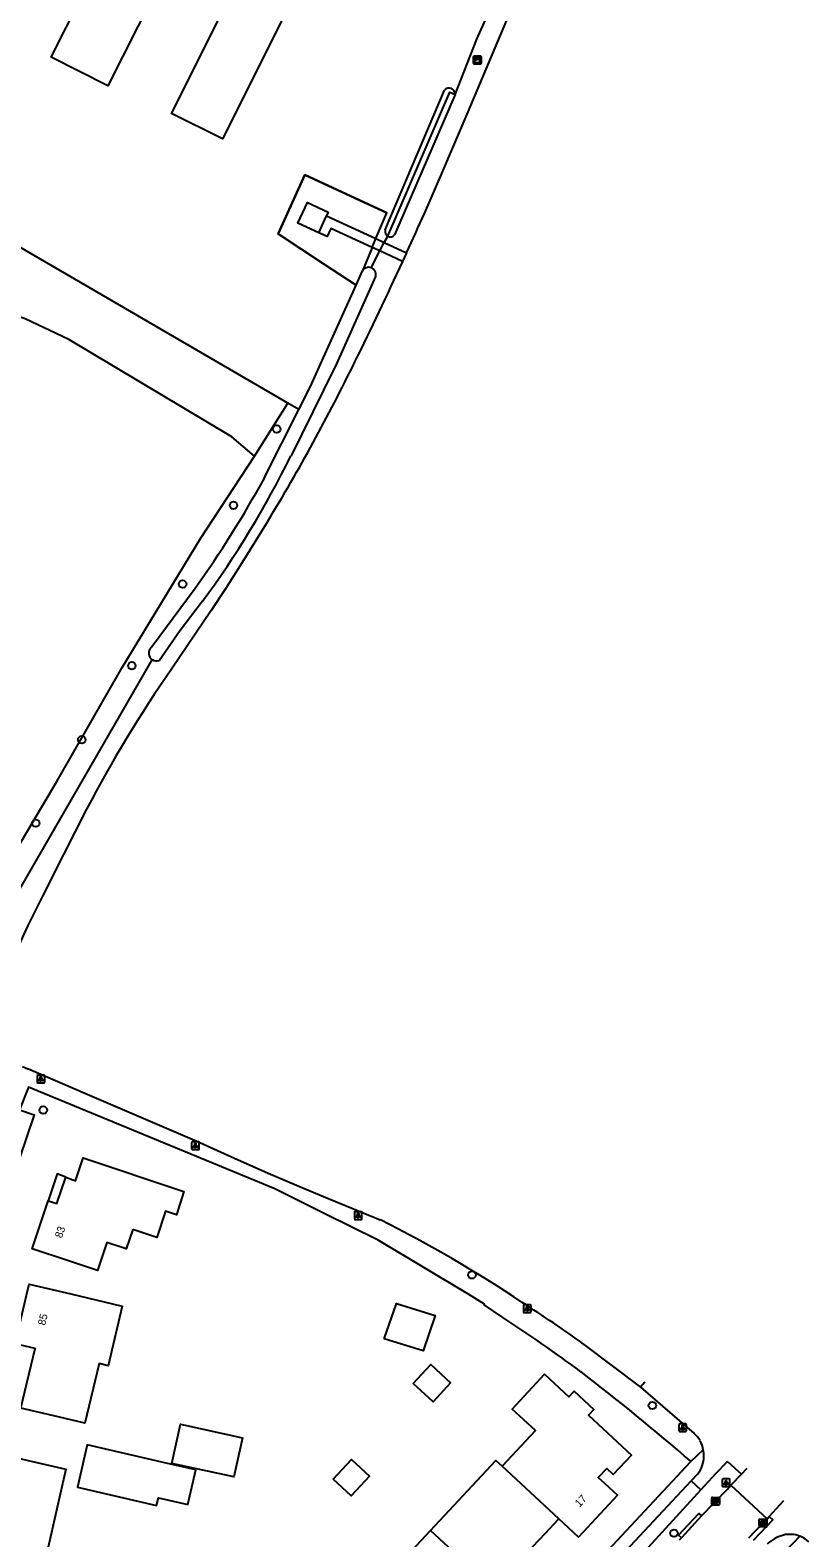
# Model space of a CAD drawing. Extents: x 159628 to 160723, y 388176 to 389416.
# Drawn here: x 160461.7 to 160563.3, y 388718.2 to 388915 of the extents above; entities that cross this region are included whole.
import ezdxf

# ---------------------------------------------------------------- set-up
doc = ezdxf.new("R2010")
doc.units = 0
for name, color, linetype in [('IMGEO_Berm_groen', 7, 'Continuous'), ('IMGEO_Boom', 7, 'Continuous'), ('IMGEO_Fietspad_gesloten', 7, 'Continuous'), ('IMGEO_Fietspad_open', 7, 'Continuous'), ('IMGEO_Grasland_overig', 7, 'Continuous'), ('IMGEO_Groenvoorziening', 7, 'Continuous'), ('IMGEO_Hek', 7, 'Continuous'), ('IMGEO_Kast', 7, 'Continuous'), ('IMGEO_Kolk', 7, 'Continuous'), ('IMGEO_Lichtpunt', 7, 'Continuous'), ('IMGEO_Pand', 7, 'Continuous'), ('IMGEO_Pand_nummerreeks', 7, 'Continuous'), ('IMGEO_Pand_overbouw', 7, 'Continuous'), ('IMGEO_Rijbaan_lokaal_gesloten', 7, 'Continuous'), ('IMGEO_Voetpad_open', 7, 'Continuous'), ('IMGEO_Waterloop', 7, 'Continuous')]:
    doc.layers.add(name, color=color, linetype=linetype)

msp = doc.modelspace()

# ---------------------------------------------------------------- linework, layer by layer
at = {"layer": 'IMGEO_Berm_groen'}
for points in [[(160517.16, 388906.59), (160520.01, 388913.81), (160524.83, 388924.6), (160525.32, 388925.76)], [(160507.93, 388887.24), (160508.38, 388888.09)], [(160506.2, 388883.96), (160507.35, 388886.15)], [(160458.13, 388798.91), (160477.65, 388832.79)]]:
    msp.add_lwpolyline(points, dxfattribs=at)
at = {"layer": 'IMGEO_Boom'}
for centre in [(160493.89, 388862.9), (160488.26, 388852.95), (160481.62, 388842.67), (160474.99, 388832.01), (160468.46, 388822.35), (160462.45, 388811.45), (160463.44, 388774), (160519.36, 388752.48), (160542.9, 388735.43), (160545.72, 388718.76)]:
    msp.add_circle(centre, 0.489, dxfattribs=at)
at = {"layer": 'IMGEO_Fietspad_gesloten'}
for points in [[(160467.55, 388639.4), (160500, 388674.18), (160547.97, 388725.59)], [(160549.23, 388724.42), (160539.1, 388713.34)], [(160547.97, 388725.59), (160549.23, 388724.42)]]:
    msp.add_lwpolyline(points, dxfattribs=at)
at = {"layer": 'IMGEO_Fietspad_open'}
for points in [[(160460.73, 388779.7), (160461.43, 388779.4), (160461.53, 388779.36), (160469.18, 388776.08), (160483.47, 388769.95), (160488.4, 388767.71), (160492.77, 388765.76), (160497.6, 388763.72), (160500, 388762.72), (160507.41, 388759.65)], [(160533.98, 388743.41), (160541.35, 388737.81)], [(160541.9, 388738.46), (160541.35, 388737.81)], [(160541.35, 388737.81), (160548.37, 388731.76)], [(160548.83, 388726.51), (160547.97, 388725.59)], [(160549.23, 388724.42), (160551.24, 388726.59), (160552.56, 388727.99)], [(160552.74, 388728.06), (160554.52, 388726.47)], [(160558.16, 388720.93), (160558.61, 388720.51), (160556.06, 388717.8)]]:
    msp.add_lwpolyline(points, dxfattribs=at)
for centre, radius, start, end in [((160429.66, 388604.48), 173.56, 56.3132, 63.3843), ((160428.46, 388597.07), 180.41, 54.2082, 57.3024), ((160546, 388728.96), 3.67, 30.822, 49.7953), ((160545.53, 388728.95), 4.08, 9.9231, 27.527), ((160546.07, 388728.72), 3.54, 321.3137, 0.6759), ((160545.43, 388728.94), 4.18, 357.558, 9.866), ((160552.87, 388727.42), 0.657, 101.5556, 118.808), ((160561.21, 388713.79), 4.87, 104.032, 133.2299), ((160560.82, 388714.9), 3.71, 69.5086, 102.3318), ((160560.82, 388714.89), 3.71, 47.7384, 69.4491)]:
    msp.add_arc(centre, radius, start, end, dxfattribs=at)
at = {"layer": 'IMGEO_Grasland_overig'}
for points in [[(160495.33, 388866.28), (160494.09, 388867.01), (160453.98, 388890.34)], [(160490.98, 388859.35), (160488.04, 388861.88), (160466.79, 388874.6), (160461.06, 388877.29), (160458.44, 388878.15), (160457.43, 388878.22), (160456.51, 388878.16), (160455.61, 388877.93), (160454.89, 388877.44), (160453.77, 388876.17), (160452.99, 388874.97), (160451.09, 388870.33), (160447.08, 388862.2), (160437.98, 388844.08), (160422.81, 388815.37), (160419.67, 388809.45), (160420.24, 388802.57)], [(160490.98, 388859.35), (160495.33, 388866.28)], [(160496.79, 388865.44), (160495.33, 388866.28)], [(160451.1, 388791.41), (160458.09, 388804.82), (160465.22, 388816.91), (160473.75, 388831.76), (160483.97, 388848.61), (160490.98, 388859.35)]]:
    msp.add_lwpolyline(points, dxfattribs=at)
at = {"layer": 'IMGEO_Groenvoorziening'}
for points in [[(160506.81, 388887.76), (160508.25, 388891.15), (160500, 388894.96), (160497.54, 388896.1), (160494.09, 388888.4), (160500, 388884.49), (160504.24, 388881.69)], [(160506.33, 388886.62), (160505.07, 388883.57)]]:
    msp.add_lwpolyline(points, dxfattribs=at)
at = {"layer": 'IMGEO_Hek'}
msp.add_lwpolyline([(160504.24, 388881.69), (160500, 388884.49), (160494.09, 388888.4), (160497.54, 388896.1), (160500, 388894.96), (160508.25, 388891.15)], dxfattribs=at)
at = {"layer": 'IMGEO_Kast'}
for p, q in [((160519.57, 388910.66), (160519.57, 388911.5)), ((160519.57, 388911.5), (160519.57, 388910.66)), ((160519.64, 388911.58), (160520.48, 388911.58)), ((160520.48, 388911.58), (160519.64, 388911.58)), ((160520.56, 388911.51), (160520.56, 388910.67)), ((160520.56, 388910.67), (160520.56, 388911.51)), ((160520.49, 388910.58), (160519.65, 388910.58)), ((160519.65, 388910.58), (160520.49, 388910.58))]:
    msp.add_line(p, q, dxfattribs=at)
for points in [[(160519.76, 388911.37), (160520.36, 388911.37), (160520.36, 388911.29), (160519.76, 388911.29), (160519.76, 388911.37)], [(160519.76, 388911.2), (160520.36, 388911.2), (160520.36, 388910.71), (160519.76, 388910.71), (160519.76, 388911.2)]]:
    msp.add_lwpolyline(points, dxfattribs=at)
msp.add_circle((160519.84, 388911.05), 0.0377, dxfattribs=at)
for centre, start, end in [((160519.64, 388911.5), 92.4484, 184.2845), ((160519.64, 388911.5), 92.4484, 184.2845), ((160520.49, 388911.5), 2.4484, 94.2845), ((160520.49, 388911.5), 2.4484, 94.2845), ((160519.64, 388910.66), 182.4484, 274.2845), ((160519.64, 388910.66), 182.4484, 274.2845), ((160520.49, 388910.66), 272.4484, 4.2845), ((160520.49, 388910.66), 272.4484, 4.2845)]:
    msp.add_arc(centre, 0.0779, start, end, dxfattribs=at)
at = {"layer": 'IMGEO_Kolk'}
for p, q in [((160550.66, 388722.5), (160550.66, 388723.35)), ((160550.73, 388723.42), (160551.58, 388723.42)), ((160551.58, 388722.42), (160550.73, 388722.42)), ((160551.14, 388723.2), (160551.17, 388723.2)), ((160551.17, 388722.64), (160551.14, 388722.64)), ((160551.66, 388723.35), (160551.66, 388722.5)), ((160556.84, 388719.66), (160556.84, 388720.51)), ((160556.91, 388720.58), (160557.76, 388720.58)), ((160557.84, 388720.51), (160557.84, 388719.66)), ((160557.76, 388719.58), (160556.91, 388719.58)), ((160557.32, 388720.36), (160557.35, 388720.36)), ((160557.35, 388719.8), (160557.32, 388719.8))]:
    msp.add_line(p, q, dxfattribs=at)
for points in [[(160550.66, 388722.5), (160550.66, 388723.35)], [(160550.73, 388723.42), (160551.58, 388723.42)], [(160551.58, 388722.42), (160550.73, 388722.42)], [(160550.98, 388723.12), (160551.1, 388723.12), (160551.1, 388722.97), (160551.23, 388723.12), (160551.39, 388723.12), (160551.25, 388722.97), (160551.4, 388722.72), (160551.25, 388722.72), (160551.16, 388722.89), (160551.1, 388722.82), (160551.1, 388722.72), (160550.98, 388722.72), (160550.98, 388723.12)], [(160551.66, 388723.35), (160551.66, 388722.5)], [(160556.84, 388719.66), (160556.84, 388720.51)], [(160556.91, 388720.58), (160557.76, 388720.58)], [(160557.84, 388720.51), (160557.84, 388719.66)], [(160557.76, 388719.58), (160556.91, 388719.58)], [(160557.16, 388720.28), (160557.28, 388720.28), (160557.28, 388720.13), (160557.41, 388720.28), (160557.57, 388720.28), (160557.43, 388720.13), (160557.58, 388719.88), (160557.43, 388719.88), (160557.34, 388720.05), (160557.28, 388719.98), (160557.28, 388719.88), (160557.16, 388719.88), (160557.16, 388720.28)]]:
    msp.add_lwpolyline(points, dxfattribs=at)
for centre, start, end in [((160550.73, 388723.35), 91.552, 178.448), ((160550.73, 388723.35), 91.552, 178.448), ((160550.73, 388722.5), 181.552, 268.448), ((160550.73, 388722.5), 181.552, 268.448), ((160551.58, 388723.35), 1.552, 88.448), ((160551.58, 388723.35), 1.552, 88.448), ((160551.58, 388722.5), 271.552, 358.448), ((160551.58, 388722.5), 271.552, 358.448), ((160556.91, 388720.51), 91.552, 178.448), ((160556.91, 388720.51), 91.552, 178.448), ((160557.76, 388720.51), 1.552, 88.448), ((160557.76, 388720.51), 1.552, 88.448), ((160556.91, 388719.66), 181.552, 268.448), ((160556.91, 388719.66), 181.552, 268.448), ((160557.76, 388719.66), 271.552, 358.448), ((160557.76, 388719.66), 271.552, 358.448)]:
    msp.add_arc(centre, 0.0765, start, end, dxfattribs=at)
for centre, major_axis, ratio, start_param, end_param in [((160551.14, 388722.92), (-0.387, 0.002), 0.722429, 4.712389, 7.853982), ((160551.17, 388722.92), (-0.39, 0.002), 0.717154, 1.570796, 4.712389), ((160557.32, 388720.08), (-0.387, 0.002), 0.722429, 4.712389, 7.853982), ((160557.35, 388720.08), (-0.39, 0.002), 0.717154, 1.570796, 4.712389)]:
    msp.add_ellipse(centre, major_axis=major_axis, ratio=ratio, start_param=start_param, end_param=end_param, dxfattribs=at)
at = {"layer": 'IMGEO_Lichtpunt'}
for p, q in [((160462.62, 388778.46), (160462.62, 388777.65)), ((160462.62, 388778.46), (160462.62, 388777.65)), ((160463.52, 388778.55), (160462.71, 388778.55)), ((160463.52, 388778.55), (160462.71, 388778.55)), ((160462.71, 388777.56), (160463.52, 388777.56)), ((160462.71, 388777.56), (160463.52, 388777.56)), ((160463.62, 388777.65), (160463.62, 388778.46)), ((160463.62, 388777.65), (160463.62, 388778.46)), ((160482.79, 388769.76), (160482.79, 388768.95)), ((160482.79, 388769.76), (160482.79, 388768.95)), ((160483.69, 388769.86), (160482.88, 388769.86)), ((160483.69, 388769.86), (160482.88, 388769.86)), ((160483.78, 388768.95), (160483.78, 388769.76)), ((160483.78, 388768.95), (160483.78, 388769.76)), ((160482.88, 388768.86), (160483.69, 388768.86)), ((160482.88, 388768.86), (160483.69, 388768.86)), ((160504.02, 388760.63), (160504.02, 388759.82)), ((160504.02, 388760.63), (160504.02, 388759.82)), ((160504.92, 388760.72), (160504.11, 388760.72)), ((160504.92, 388760.72), (160504.11, 388760.72)), ((160505.01, 388759.82), (160505.01, 388760.63)), ((160505.01, 388759.82), (160505.01, 388760.63)), ((160504.11, 388759.73), (160504.92, 388759.73)), ((160504.11, 388759.73), (160504.92, 388759.73)), ((160526.08, 388748.47), (160526.08, 388747.67)), ((160526.08, 388748.47), (160526.08, 388747.67)), ((160526.98, 388748.57), (160526.17, 388748.57)), ((160526.98, 388748.57), (160526.17, 388748.57)), ((160527.07, 388747.67), (160527.07, 388748.47)), ((160527.07, 388747.67), (160527.07, 388748.47)), ((160526.17, 388747.57), (160526.98, 388747.57)), ((160526.17, 388747.57), (160526.98, 388747.57)), ((160546.36, 388732.94), (160546.36, 388732.13)), ((160546.36, 388732.94), (160546.36, 388732.13)), ((160547.26, 388733.03), (160546.45, 388733.03)), ((160547.26, 388733.03), (160546.45, 388733.03)), ((160547.35, 388732.13), (160547.35, 388732.94)), ((160547.35, 388732.13), (160547.35, 388732.94)), ((160546.45, 388732.04), (160547.26, 388732.04)), ((160546.45, 388732.04), (160547.26, 388732.04)), ((160552.02, 388725.74), (160552.02, 388724.94)), ((160552.02, 388725.74), (160552.02, 388724.94)), ((160552.92, 388725.84), (160552.12, 388725.84)), ((160552.92, 388725.84), (160552.12, 388725.84)), ((160552.12, 388724.84), (160552.92, 388724.84)), ((160552.12, 388724.84), (160552.92, 388724.84)), ((160553.02, 388724.94), (160553.02, 388725.74)), ((160553.02, 388724.94), (160553.02, 388725.74))]:
    msp.add_line(p, q, dxfattribs=at)
for points in [[(160462.99, 388778.12), (160463.03, 388778.09), (160462.84, 388777.83), (160462.81, 388777.86), (160462.99, 388778.12)], [(160463.09, 388778.07), (160463.14, 388778.07), (160463.14, 388777.75), (160463.09, 388777.75), (160463.09, 388778.07)], [(160463.2, 388778.09), (160463.24, 388778.12), (160463.43, 388777.86), (160463.39, 388777.83), (160463.2, 388778.09)], [(160483.16, 388769.42), (160483.2, 388769.4), (160483.01, 388769.13), (160482.97, 388769.16), (160483.16, 388769.42)], [(160483.26, 388769.38), (160483.31, 388769.38), (160483.31, 388769.05), (160483.26, 388769.05), (160483.26, 388769.38)], [(160483.37, 388769.4), (160483.41, 388769.42), (160483.6, 388769.16), (160483.56, 388769.13), (160483.37, 388769.4)], [(160504.39, 388760.29), (160504.43, 388760.26), (160504.24, 388760), (160504.2, 388760.03), (160504.39, 388760.29)], [(160504.49, 388760.24), (160504.54, 388760.24), (160504.54, 388759.92), (160504.49, 388759.92), (160504.49, 388760.24)], [(160504.6, 388760.26), (160504.64, 388760.29), (160504.83, 388760.03), (160504.79, 388760), (160504.6, 388760.26)], [(160526.45, 388748.14), (160526.49, 388748.11), (160526.3, 388747.85), (160526.26, 388747.87), (160526.45, 388748.14)], [(160526.55, 388748.09), (160526.6, 388748.09), (160526.6, 388747.77), (160526.55, 388747.77), (160526.55, 388748.09)], [(160526.66, 388748.11), (160526.7, 388748.14), (160526.89, 388747.87), (160526.85, 388747.85), (160526.66, 388748.11)], [(160546.73, 388732.6), (160546.77, 388732.57), (160546.58, 388732.31), (160546.54, 388732.34), (160546.73, 388732.6)], [(160546.83, 388732.55), (160546.88, 388732.55), (160546.88, 388732.23), (160546.83, 388732.23), (160546.83, 388732.55)], [(160546.94, 388732.57), (160546.98, 388732.6), (160547.17, 388732.34), (160547.13, 388732.31), (160546.94, 388732.57)], [(160552.4, 388725.41), (160552.43, 388725.38), (160552.25, 388725.12), (160552.21, 388725.14), (160552.4, 388725.41)], [(160552.5, 388725.36), (160552.55, 388725.36), (160552.55, 388725.04), (160552.5, 388725.04), (160552.5, 388725.36)], [(160552.61, 388725.38), (160552.65, 388725.41), (160552.83, 388725.14), (160552.79, 388725.12), (160552.61, 388725.38)]]:
    msp.add_lwpolyline(points, dxfattribs=at)
for centre in [(160463.12, 388778.26), (160483.29, 388769.56), (160504.52, 388760.43), (160526.58, 388748.27), (160546.86, 388732.74), (160552.52, 388725.54)]:
    msp.add_circle(centre, 0.0994, dxfattribs=at)
for centre, start, end in [((160462.71, 388778.46), 90, 180), ((160462.71, 388778.46), 90, 180), ((160462.71, 388777.65), 180, 270), ((160462.71, 388777.65), 180, 270), ((160463.52, 388778.46), 0, 90), ((160463.52, 388778.46), 0, 90), ((160463.52, 388777.65), 270, 0), ((160463.52, 388777.65), 270, 360), ((160482.88, 388769.76), 90, 180), ((160482.88, 388769.76), 90, 180), ((160483.69, 388769.76), 0, 90), ((160483.69, 388769.76), 0, 90), ((160482.88, 388768.95), 180, 270), ((160482.88, 388768.95), 180, 270), ((160483.69, 388768.95), 270, 0), ((160483.69, 388768.95), 270, 360), ((160504.11, 388760.63), 90, 180), ((160504.11, 388760.63), 90, 180), ((160504.11, 388759.82), 180, 270), ((160504.11, 388759.82), 180, 270), ((160504.92, 388760.63), 0, 90), ((160504.92, 388760.63), 0, 90), ((160504.92, 388759.82), 270, 0), ((160504.92, 388759.82), 270, 360), ((160526.17, 388748.47), 90, 180), ((160526.17, 388748.47), 90, 180), ((160526.98, 388748.47), 0, 90), ((160526.98, 388748.47), 0, 90), ((160526.17, 388747.67), 180, 270), ((160526.17, 388747.67), 180, 270), ((160526.98, 388747.67), 270, 0), ((160526.98, 388747.67), 270, 360), ((160546.45, 388732.94), 90, 180), ((160546.45, 388732.94), 90, 180), ((160547.26, 388732.94), 0, 90), ((160547.26, 388732.94), 0, 90), ((160546.45, 388732.13), 180, 270), ((160546.45, 388732.13), 180, 270), ((160547.26, 388732.13), 270, 0), ((160547.26, 388732.13), 270, 360), ((160552.12, 388725.74), 90, 180), ((160552.12, 388725.74), 90, 180), ((160552.12, 388724.94), 180, 270), ((160552.12, 388724.94), 180, 270), ((160552.92, 388725.74), 0, 90), ((160552.92, 388725.74), 0, 90), ((160552.92, 388724.94), 270, 0), ((160552.92, 388724.94), 270, 360)]:
    msp.add_arc(centre, 0.0946, start, end, dxfattribs=at)
at = {"layer": 'IMGEO_Pand'}
for points in [[(160481.65, 388927.13), (160471.88, 388907.7), (160464.48, 388911.43), (160474.24, 388930.85), (160481.65, 388927.13)], [(160496.43, 388920.01), (160486.82, 388900.78), (160480.17, 388904.11), (160489.78, 388923.33), (160496.43, 388920.01)], [(160499.37, 388888.5), (160496.65, 388889.78), (160497.91, 388892.48), (160500.6, 388891.21), (160500.38, 388890.73)], [(160499.37, 388888.5), (160500.38, 388890.73)], [(160475.1, 388758.39), (160474.27, 388755.87), (160471.71, 388756.72), (160470.49, 388753.06), (160466.71, 388754.32), (160461.97, 388755.9), (160464.06, 388762.17), (160465.2, 388761.79), (160466.38, 388765.24), (160467.62, 388764.78), (160468.64, 388767.76), (160481.79, 388763.35), (160480.8, 388760.31), (160479.38, 388760.78), (160478.24, 388757.35), (160475.1, 388758.39)], [(160460.52, 388735.1), (160462.37, 388742.89), (160459.76, 388743.5), (160461.3, 388750), (160461.6, 388751.28), (160466.47, 388750.13), (160467.03, 388750), (160473.75, 388748.41), (160471.89, 388740.62), (160470.72, 388740.9), (160468.88, 388733.12), (160465.39, 388733.95), (160460.52, 388735.1)], [(160507.93, 388744.13), (160509.52, 388748.75), (160514.58, 388747.18), (160512.99, 388742.55), (160507.93, 388744.13)], [(160511.71, 388738.32), (160513.98, 388740.79), (160516.58, 388738.39), (160514.31, 388735.93), (160511.71, 388738.32)], [(160523.29, 388727.49), (160523.4, 388727.6), (160527.64, 388732.16), (160524.62, 388734.94), (160528.83, 388739.51), (160532, 388736.57), (160532.68, 388737.31), (160535.28, 388734.9), (160534.58, 388734.15), (160540.18, 388728.94), (160537.78, 388726.42), (160536.95, 388727.21), (160535.84, 388726.05), (160536.66, 388725.29), (160538.37, 388723.72), (160533.25, 388718.25), (160530.69, 388720.62)], [(160480.19, 388727.88), (160481.32, 388733.01), (160489.44, 388731.22), (160488.32, 388726.1), (160480.19, 388727.88)], [(160483.32, 388727.02), (160479.48, 388727.9), (160469.17, 388730.28), (160467.9, 388724.75), (160478.23, 388722.39), (160478.45, 388723.37), (160482.29, 388722.5), (160483.32, 388727.02)], [(160463.35, 388713.66), (160459.42, 388714.55), (160454.54, 388715.66), (160455.78, 388721.05), (160455.28, 388721.17), (160455.36, 388721.49), (160455.86, 388721.37), (160456.39, 388723.63), (160455.89, 388723.74), (160457.16, 388729.24), (160462.04, 388728.12), (160466.4, 388727.12), (160463.35, 388713.66)], [(160501.27, 388725.8), (160503.66, 388728.37), (160505.99, 388726.19), (160503.6, 388723.62), (160501.27, 388725.8)], [(160513.95, 388719.12), (160522.46, 388728.26), (160523.29, 388727.49)], [(160530.69, 388720.62), (160523.29, 388727.49)], [(160530.69, 388720.62), (160530.57, 388720.49), (160528.91, 388718.71), (160527.24, 388716.94), (160528.95, 388715.38), (160523.85, 388709.91), (160522.17, 388711.48)], [(160505.43, 388709.97), (160513.95, 388719.12)], [(160522.17, 388711.48), (160513.95, 388719.12)]]:
    msp.add_lwpolyline(points, dxfattribs=at)
at = {"layer": 'IMGEO_Pand_overbouw'}
msp.add_lwpolyline([(160466.38, 388765.24), (160465.26, 388765.66), (160464.06, 388762.17), (160465.2, 388761.79)], close=True, dxfattribs=at)
at = {"layer": 'IMGEO_Rijbaan_lokaal_gesloten'}
for points in [[(160526.52, 388922.78), (160525.93, 388921.41), (160523.89, 388916.29), (160518.83, 388904.33), (160515.37, 388896.26), (160513.19, 388891.13)], [(160510.84, 388885.9), (160510.32, 388884.78)], [(160492.73, 388850.88), (160489.6, 388845.85), (160487.19, 388842.04), (160485.34, 388839.23), (160480.17, 388831.54)], [(160469.08, 388813.26), (160466.1, 388807.43), (160463.33, 388801.91), (160461.41, 388798.08), (160458.6, 388791.93)], [(160554.52, 388726.47), (160553.16, 388725.02)], [(160554.52, 388726.47), (160555.26, 388727.26)], [(160549.33, 388721.01), (160552.7, 388724.53), (160553.16, 388725.02)], [(160553.16, 388725.02), (160557.86, 388720.62)], [(160558.16, 388720.93), (160560.05, 388723.01)], [(160549.33, 388721.01), (160546.7, 388718.17)], [(160555.49, 388718.14), (160557.27, 388720.03), (160557.86, 388720.62)], [(160557.86, 388720.62), (160558.16, 388720.93)], [(160546.45, 388717.9), (160546.7, 388718.17)]]:
    msp.add_lwpolyline(points, dxfattribs=at)
for centre, radius, start, end in [((159988.5, 389124.54), 574.27, 335.44608, 336.01825), ((160006.86, 389116.13), 554.08, 333.819, 335.3205), ((160280.54, 388980.32), 248.55, 328.6155, 334.0778), ((160615.33, 388737.13), 164.87, 145.0624, 152.4992)]:
    msp.add_arc(centre, radius, start, end, dxfattribs=at)
at = {"layer": 'IMGEO_Voetpad_open'}
for points in [[(160500.38, 388890.73), (160506.81, 388887.76)], [(160506.33, 388886.62), (160500.97, 388889.1), (160500.47, 388888.03), (160499.37, 388888.5)], [(160506.33, 388886.62), (160506.81, 388887.76)], [(160506.81, 388887.76), (160507.93, 388887.24)], [(160507.35, 388886.15), (160506.33, 388886.62)], [(160507.35, 388886.15), (160507.93, 388887.24)], [(160510.32, 388884.78), (160507.35, 388886.15)], [(160507.93, 388887.24), (160510.84, 388885.9)], [(160523.27, 388747), (160520.96, 388748.57), (160521.02, 388748.68), (160518.82, 388750), (160507.11, 388757), (160500, 388760.56), (160493.66, 388763.73), (160468.25, 388774.2), (160461.52, 388776.98), (160460.33, 388774.04)], [(160460.33, 388774.04), (160462.23, 388773.36), (160460.35, 388767.73)], [(160549.55, 388729.66), (160547.94, 388728.11)], [(160467.48, 388641.82), (160500, 388676.7), (160547.94, 388728.11)], [(160546.7, 388718.17), (160546.33, 388718.51), (160548.96, 388721.35), (160549.33, 388721.01)], [(160562.12, 388718.37), (160560.21, 388716.38)]]:
    msp.add_lwpolyline(points, dxfattribs=at)
for centre, radius, start, end in [((160393.76, 388549.79), 235.94, 53.6604, 56.7066), ((160334.34, 388480.99), 326.65, 49.1608, 52.4164)]:
    msp.add_arc(centre, radius, start, end, dxfattribs=at)
at = {"layer": 'IMGEO_Waterloop'}
for points in [[(160508.05, 388888.9), (160515.78, 388907.16)], [(160508.38, 388888.09), (160516.49, 388906.88), (160517.16, 388906.59)], [(160517.16, 388906.59), (160509.27, 388888.26)], [(160506.8, 388882.83), (160501.7, 388871.43), (160500, 388867.99), (160495.76, 388859.4)], [(160504.24, 388881.69), (160505.07, 388883.57)], [(160496.79, 388865.44), (160498.32, 388868.47), (160500, 388872.23), (160504.24, 388881.69)], [(160492.32, 388856.58), (160496.79, 388865.44)], [(160477.5, 388834.38), (160483.24, 388842.13)], [(160484.23, 388840.43), (160481.3, 388836.6), (160478.54, 388832.66)]]:
    msp.add_lwpolyline(points, dxfattribs=at)
for centre, radius, start, end in [((160516.37, 388906.63), 0.795, 357.0729, 137.4753), ((160508.73, 388888.7), 0.704, 163.6365, 240.0641), ((160508.72, 388888.7), 0.701, 240.1085, 321.3544), ((160505.88, 388883.07), 0.953, 70.141, 148.475), ((160505.88, 388883.07), 0.952, 345.7174, 70.0585), ((160380.68, 388916.34), 128.39, 323.7526, 333.6728), ((160367.64, 388924.82), 142.14, 324.4216, 331.305), ((160478.23, 388833.65), 1.04, 135.1183, 235.8884), ((160478.23, 388833.65), 1.03, 235.8537, 287.3626)]:
    msp.add_arc(centre, radius, start, end, dxfattribs=at)

# ---------------------------------------------------------------- texts
at = {"layer": 'IMGEO_Pand_nummerreeks'}
for s, rotation, p in [('83', 71.5395, (160465.86, 388757.21)), ('85', 76.6536, (160463.68, 388745.83)), ('17', 46.9081, (160533.41, 388722.1))]:
    msp.add_text(s, height=1, rotation=rotation, dxfattribs=at).set_placement(p)

doc.saveas('drawing.dxf')
